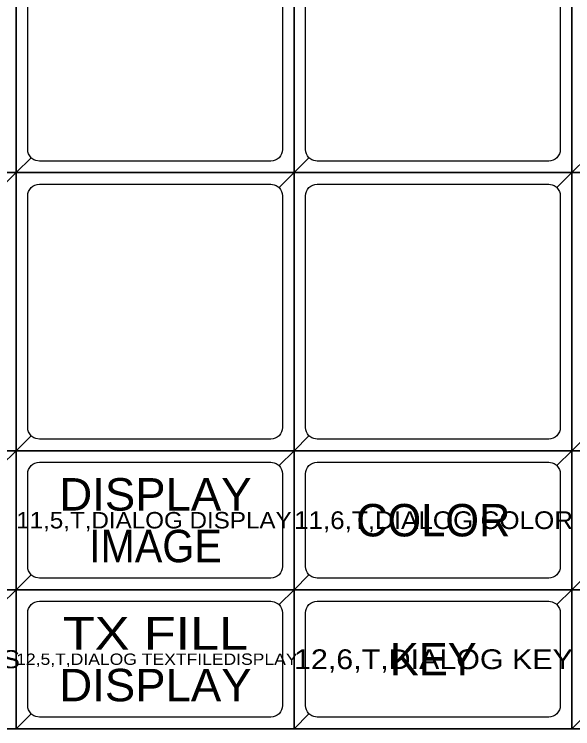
# Model space of a CAD drawing. Extents: x 67896 to 67908, y 49158.5 to 49162.6.
# Drawn here: x 67898.685 to 67899.891, y 49159.033 to 49160.575 of the extents above; entities that cross this region are included whole.
import ezdxf
from ezdxf.enums import TextEntityAlignment as Align

# ---------------------------------------------------------------- set-up
doc = ezdxf.new("R2010")
doc.units = 0
doc.header["$LTSCALE"] = 0.02
for name, color, linetype, lineweight in [('1', 7, 'Continuous', 25), ('2', 7, 'Continuous', 25), ('3', 7, 'Continuous', 25), ('4', 7, 'Continuous', 25), ('5', 7, 'Continuous', 25)]:
    doc.layers.add(name, color=color, linetype=linetype, lineweight=lineweight)
doc.layers.add('63', color=7, linetype='Continuous')

msp = doc.modelspace()

# ---------------------------------------------------------------- linework, layer by layer
at = {"layer": '1'}
for points in [[(67898.0889, 49160.2331), (67898.6889, 49160.2331), (67898.6889, 49160.8331), (67898.0889, 49160.8331)], [(67898.6889, 49160.2331), (67899.2889, 49160.2331), (67899.2889, 49160.8331), (67898.6889, 49160.8331)], [(67899.2889, 49160.2331), (67899.8889, 49160.2331), (67899.8889, 49160.8331), (67899.2889, 49160.8331)], [(67899.8889, 49160.2331), (67900.4889, 49160.2331), (67900.4889, 49160.8331), (67899.8889, 49160.8331)], [(67898.0889, 49159.6331), (67898.6889, 49159.6331), (67898.6889, 49160.2331), (67898.0889, 49160.2331)], [(67898.6889, 49159.6331), (67899.2889, 49159.6331), (67899.2889, 49160.2331), (67898.6889, 49160.2331)], [(67899.2889, 49159.6331), (67899.8889, 49159.6331), (67899.8889, 49160.2331), (67899.2889, 49160.2331)], [(67899.8889, 49159.6331), (67900.4889, 49159.6331), (67900.4889, 49160.2331), (67899.8889, 49160.2331)], [(67898.0889, 49159.3331), (67898.6889, 49159.3331), (67898.6889, 49159.6331), (67898.0889, 49159.6331)], [(67898.6889, 49159.3331), (67899.2889, 49159.3331), (67899.2889, 49159.6331), (67898.6889, 49159.6331)], [(67899.2889, 49159.3331), (67899.8889, 49159.3331), (67899.8889, 49159.6331), (67899.2889, 49159.6331)], [(67899.8889, 49159.3331), (67900.4889, 49159.3331), (67900.4889, 49159.6331), (67899.8889, 49159.6331)], [(67898.0889, 49159.0331), (67898.6889, 49159.0331), (67898.6889, 49159.3331), (67898.0889, 49159.3331)], [(67898.6889, 49159.0331), (67899.2889, 49159.0331), (67899.2889, 49159.3331), (67898.6889, 49159.3331)], [(67899.2889, 49159.0331), (67899.8889, 49159.0331), (67899.8889, 49159.3331), (67899.2889, 49159.3331)], [(67899.8889, 49159.0331), (67900.4889, 49159.0331), (67900.4889, 49159.3331), (67899.8889, 49159.3331)]]:
    msp.add_lwpolyline(points, close=True, dxfattribs=at)
at = {"layer": '2'}
for points in [[(67907.9889, 49159.0331), (67895.9889, 49159.0331), (67895.9889, 49162.6331), (67907.9889, 49162.6331)], [(67898.0889, 49160.2331), (67898.6889, 49160.2331), (67898.6889, 49160.8331), (67898.0889, 49160.8331)], [(67898.6889, 49160.2331), (67899.2889, 49160.2331), (67899.2889, 49160.8331), (67898.6889, 49160.8331)], [(67899.2889, 49160.2331), (67899.8889, 49160.2331), (67899.8889, 49160.8331), (67899.2889, 49160.8331)], [(67899.8889, 49160.2331), (67900.4889, 49160.2331), (67900.4889, 49160.8331), (67899.8889, 49160.8331)], [(67898.0889, 49159.6331), (67898.6889, 49159.6331), (67898.6889, 49160.2331), (67898.0889, 49160.2331)], [(67898.6889, 49159.6331), (67899.2889, 49159.6331), (67899.2889, 49160.2331), (67898.6889, 49160.2331)], [(67899.2889, 49159.6331), (67899.8889, 49159.6331), (67899.8889, 49160.2331), (67899.2889, 49160.2331)], [(67899.8889, 49159.6331), (67900.4889, 49159.6331), (67900.4889, 49160.2331), (67899.8889, 49160.2331)], [(67898.0889, 49159.3331), (67898.6889, 49159.3331), (67898.6889, 49159.6331), (67898.0889, 49159.6331)], [(67898.6889, 49159.3331), (67899.2889, 49159.3331), (67899.2889, 49159.6331), (67898.6889, 49159.6331)], [(67899.2889, 49159.3331), (67899.8889, 49159.3331), (67899.8889, 49159.6331), (67899.2889, 49159.6331)], [(67899.8889, 49159.3331), (67900.4889, 49159.3331), (67900.4889, 49159.6331), (67899.8889, 49159.6331)], [(67898.0889, 49159.0331), (67898.6889, 49159.0331), (67898.6889, 49159.3331), (67898.0889, 49159.3331)], [(67898.6889, 49159.0331), (67899.2889, 49159.0331), (67899.2889, 49159.3331), (67898.6889, 49159.3331)], [(67899.2889, 49159.0331), (67899.8889, 49159.0331), (67899.8889, 49159.3331), (67899.2889, 49159.3331)], [(67899.8889, 49159.0331), (67900.4889, 49159.0331), (67900.4889, 49159.3331), (67899.8889, 49159.3331)]]:
    msp.add_lwpolyline(points, close=True, dxfattribs=at)
at = {"layer": '3'}
for points in [[(67899.2889, 49160.8331), (67898.6889, 49160.8331), (67898.6889, 49160.2331), (67898.7212, 49160.2654), (67898.7181, 49160.2692), (67898.7158, 49160.2735), (67898.7144, 49160.2782), (67898.7139, 49160.2831), (67898.7139, 49160.7831), (67898.7144, 49160.788), (67898.7158, 49160.7927), (67898.7181, 49160.797), (67898.7212, 49160.8008), (67898.7212, 49160.8008), (67898.725, 49160.8039), (67898.7293, 49160.8062), (67898.734, 49160.8076), (67898.7389, 49160.8081), (67899.2389, 49160.8081), (67899.2462, 49160.807), (67899.2507, 49160.8051), (67899.2548, 49160.8024), (67899.2566, 49160.8008)], [(67899.8889, 49160.8331), (67899.2889, 49160.8331), (67899.2889, 49160.2331), (67899.3212, 49160.2654), (67899.3181, 49160.2692), (67899.3158, 49160.2735), (67899.3144, 49160.2782), (67899.3139, 49160.2831), (67899.3139, 49160.7831), (67899.3144, 49160.788), (67899.3158, 49160.7927), (67899.3181, 49160.797), (67899.3212, 49160.8008), (67899.3212, 49160.8008), (67899.325, 49160.8039), (67899.3293, 49160.8062), (67899.334, 49160.8076), (67899.3389, 49160.8081), (67899.8389, 49160.8081), (67899.8462, 49160.807), (67899.8507, 49160.8051), (67899.8548, 49160.8024), (67899.8566, 49160.8008)], [(67900.4889, 49160.8331), (67899.8889, 49160.8331), (67899.8889, 49160.2331), (67899.9212, 49160.2654), (67899.9181, 49160.2692), (67899.9158, 49160.2735), (67899.9144, 49160.2782), (67899.9139, 49160.2831), (67899.9139, 49160.7831), (67899.9144, 49160.788), (67899.9158, 49160.7927), (67899.9181, 49160.797), (67899.9212, 49160.8008), (67899.9212, 49160.8008), (67899.925, 49160.8039), (67899.9293, 49160.8062), (67899.934, 49160.8076), (67899.9389, 49160.8081), (67900.4389, 49160.8081), (67900.4462, 49160.807), (67900.4507, 49160.8051), (67900.4548, 49160.8024), (67900.4566, 49160.8008)], [(67898.6889, 49160.2331), (67898.0889, 49160.2331), (67898.0889, 49159.6331), (67898.1212, 49159.6654), (67898.1181, 49159.6692), (67898.1158, 49159.6735), (67898.1144, 49159.6782), (67898.1139, 49159.6831), (67898.1139, 49160.1831), (67898.1144, 49160.188), (67898.1158, 49160.1927), (67898.1181, 49160.197), (67898.1212, 49160.2008), (67898.1212, 49160.2008), (67898.125, 49160.2039), (67898.1293, 49160.2062), (67898.134, 49160.2076), (67898.1389, 49160.2081), (67898.6389, 49160.2081), (67898.6462, 49160.207), (67898.6507, 49160.2051), (67898.6548, 49160.2024), (67898.6566, 49160.2008)], [(67899.2889, 49160.2331), (67898.6889, 49160.2331), (67898.6889, 49159.6331), (67898.7212, 49159.6654), (67898.7181, 49159.6692), (67898.7158, 49159.6735), (67898.7144, 49159.6782), (67898.7139, 49159.6831), (67898.7139, 49160.1831), (67898.7144, 49160.188), (67898.7158, 49160.1927), (67898.7181, 49160.197), (67898.7212, 49160.2008), (67898.7212, 49160.2008), (67898.725, 49160.2039), (67898.7293, 49160.2062), (67898.734, 49160.2076), (67898.7389, 49160.2081), (67899.2389, 49160.2081), (67899.2462, 49160.207), (67899.2507, 49160.2051), (67899.2548, 49160.2024), (67899.2566, 49160.2008)], [(67899.8889, 49160.2331), (67899.2889, 49160.2331), (67899.2889, 49159.6331), (67899.3212, 49159.6654), (67899.3181, 49159.6692), (67899.3158, 49159.6735), (67899.3144, 49159.6782), (67899.3139, 49159.6831), (67899.3139, 49160.1831), (67899.3144, 49160.188), (67899.3158, 49160.1927), (67899.3181, 49160.197), (67899.3212, 49160.2008), (67899.3212, 49160.2008), (67899.325, 49160.2039), (67899.3293, 49160.2062), (67899.334, 49160.2076), (67899.3389, 49160.2081), (67899.8389, 49160.2081), (67899.8462, 49160.207), (67899.8507, 49160.2051), (67899.8548, 49160.2024), (67899.8566, 49160.2008)], [(67900.4889, 49160.2331), (67899.8889, 49160.2331), (67899.8889, 49159.6331), (67899.9212, 49159.6654), (67899.9181, 49159.6692), (67899.9158, 49159.6735), (67899.9144, 49159.6782), (67899.9139, 49159.6831), (67899.9139, 49160.1831), (67899.9144, 49160.188), (67899.9158, 49160.1927), (67899.9181, 49160.197), (67899.9212, 49160.2008), (67899.9212, 49160.2008), (67899.925, 49160.2039), (67899.9293, 49160.2062), (67899.934, 49160.2076), (67899.9389, 49160.2081), (67900.4389, 49160.2081), (67900.4462, 49160.207), (67900.4507, 49160.2051), (67900.4548, 49160.2024), (67900.4566, 49160.2008)], [(67898.6889, 49159.6331), (67898.0889, 49159.6331), (67898.0889, 49159.3331), (67898.1212, 49159.3654), (67898.1181, 49159.3692), (67898.1158, 49159.3735), (67898.1144, 49159.3782), (67898.1139, 49159.3831), (67898.1139, 49159.5831), (67898.1144, 49159.588), (67898.1158, 49159.5927), (67898.1181, 49159.597), (67898.1212, 49159.6008), (67898.1212, 49159.6008), (67898.125, 49159.6039), (67898.1293, 49159.6062), (67898.134, 49159.6076), (67898.1389, 49159.6081), (67898.6389, 49159.6081), (67898.6462, 49159.607), (67898.6507, 49159.6051), (67898.6548, 49159.6024), (67898.6566, 49159.6008)], [(67899.2889, 49159.6331), (67898.6889, 49159.6331), (67898.6889, 49159.3331), (67898.7212, 49159.3654), (67898.7181, 49159.3692), (67898.7158, 49159.3735), (67898.7144, 49159.3782), (67898.7139, 49159.3831), (67898.7139, 49159.5831), (67898.7144, 49159.588), (67898.7158, 49159.5927), (67898.7181, 49159.597), (67898.7212, 49159.6008), (67898.7212, 49159.6008), (67898.725, 49159.6039), (67898.7293, 49159.6062), (67898.734, 49159.6076), (67898.7389, 49159.6081), (67899.2389, 49159.6081), (67899.2462, 49159.607), (67899.2507, 49159.6051), (67899.2548, 49159.6024), (67899.2566, 49159.6008)], [(67899.8889, 49159.6331), (67899.2889, 49159.6331), (67899.2889, 49159.3331), (67899.3212, 49159.3654), (67899.3181, 49159.3692), (67899.3158, 49159.3735), (67899.3144, 49159.3782), (67899.3139, 49159.3831), (67899.3139, 49159.5831), (67899.3144, 49159.588), (67899.3158, 49159.5927), (67899.3181, 49159.597), (67899.3212, 49159.6008), (67899.3212, 49159.6008), (67899.325, 49159.6039), (67899.3293, 49159.6062), (67899.334, 49159.6076), (67899.3389, 49159.6081), (67899.8389, 49159.6081), (67899.8462, 49159.607), (67899.8507, 49159.6051), (67899.8548, 49159.6024), (67899.8566, 49159.6008)], [(67900.4889, 49159.6331), (67899.8889, 49159.6331), (67899.8889, 49159.3331), (67899.9212, 49159.3654), (67899.9181, 49159.3692), (67899.9158, 49159.3735), (67899.9144, 49159.3782), (67899.9139, 49159.3831), (67899.9139, 49159.5831), (67899.9144, 49159.588), (67899.9158, 49159.5927), (67899.9181, 49159.597), (67899.9212, 49159.6008), (67899.9212, 49159.6008), (67899.925, 49159.6039), (67899.9293, 49159.6062), (67899.934, 49159.6076), (67899.9389, 49159.6081), (67900.4389, 49159.6081), (67900.4462, 49159.607), (67900.4507, 49159.6051), (67900.4548, 49159.6024), (67900.4566, 49159.6008)], [(67898.6889, 49159.3331), (67898.0889, 49159.3331), (67898.0889, 49159.0331), (67898.1212, 49159.0654), (67898.1181, 49159.0692), (67898.1158, 49159.0735), (67898.1144, 49159.0782), (67898.1139, 49159.0831), (67898.1139, 49159.2831), (67898.1144, 49159.288), (67898.1158, 49159.2927), (67898.1181, 49159.297), (67898.1212, 49159.3008), (67898.1212, 49159.3008), (67898.125, 49159.3039), (67898.1293, 49159.3062), (67898.134, 49159.3076), (67898.1389, 49159.3081), (67898.6389, 49159.3081), (67898.6462, 49159.307), (67898.6507, 49159.3051), (67898.6548, 49159.3024), (67898.6566, 49159.3008)], [(67899.2889, 49159.3331), (67898.6889, 49159.3331), (67898.6889, 49159.0331), (67898.7212, 49159.0654), (67898.7181, 49159.0692), (67898.7158, 49159.0735), (67898.7144, 49159.0782), (67898.7139, 49159.0831), (67898.7139, 49159.2831), (67898.7144, 49159.288), (67898.7158, 49159.2927), (67898.7181, 49159.297), (67898.7212, 49159.3008), (67898.7212, 49159.3008), (67898.725, 49159.3039), (67898.7293, 49159.3062), (67898.734, 49159.3076), (67898.7389, 49159.3081), (67899.2389, 49159.3081), (67899.2462, 49159.307), (67899.2507, 49159.3051), (67899.2548, 49159.3024), (67899.2566, 49159.3008)], [(67899.8889, 49159.3331), (67899.2889, 49159.3331), (67899.2889, 49159.0331), (67899.3212, 49159.0654), (67899.3181, 49159.0692), (67899.3158, 49159.0735), (67899.3144, 49159.0782), (67899.3139, 49159.0831), (67899.3139, 49159.2831), (67899.3144, 49159.288), (67899.3158, 49159.2927), (67899.3181, 49159.297), (67899.3212, 49159.3008), (67899.3212, 49159.3008), (67899.325, 49159.3039), (67899.3293, 49159.3062), (67899.334, 49159.3076), (67899.3389, 49159.3081), (67899.8389, 49159.3081), (67899.8462, 49159.307), (67899.8507, 49159.3051), (67899.8548, 49159.3024), (67899.8566, 49159.3008)], [(67900.4889, 49159.3331), (67899.8889, 49159.3331), (67899.8889, 49159.0331), (67899.9212, 49159.0654), (67899.9181, 49159.0692), (67899.9158, 49159.0735), (67899.9144, 49159.0782), (67899.9139, 49159.0831), (67899.9139, 49159.2831), (67899.9144, 49159.288), (67899.9158, 49159.2927), (67899.9181, 49159.297), (67899.9212, 49159.3008), (67899.9212, 49159.3008), (67899.925, 49159.3039), (67899.9293, 49159.3062), (67899.934, 49159.3076), (67899.9389, 49159.3081), (67900.4389, 49159.3081), (67900.4462, 49159.307), (67900.4507, 49159.3051), (67900.4548, 49159.3024), (67900.4566, 49159.3008)]]:
    msp.add_lwpolyline(points, close=True, dxfattribs=at)
at = {"layer": '4'}
for points in [[(67898.0889, 49160.2331), (67898.6889, 49160.2331), (67898.6889, 49160.8331), (67898.6566, 49160.8008), (67898.6597, 49160.797), (67898.662, 49160.7927), (67898.6634, 49160.788), (67898.6639, 49160.7831), (67898.6639, 49160.2831), (67898.6634, 49160.2782), (67898.662, 49160.2735), (67898.6597, 49160.2692), (67898.6566, 49160.2654), (67898.6566, 49160.2654), (67898.6528, 49160.2623), (67898.6485, 49160.26), (67898.6438, 49160.2586), (67898.6389, 49160.2581), (67898.1389, 49160.2581), (67898.1316, 49160.2592), (67898.1271, 49160.2611), (67898.123, 49160.2638), (67898.1212, 49160.2654)], [(67898.6889, 49160.2331), (67899.2889, 49160.2331), (67899.2889, 49160.8331), (67899.2566, 49160.8008), (67899.2597, 49160.797), (67899.262, 49160.7927), (67899.2634, 49160.788), (67899.2639, 49160.7831), (67899.2639, 49160.2831), (67899.2634, 49160.2782), (67899.262, 49160.2735), (67899.2597, 49160.2692), (67899.2566, 49160.2654), (67899.2566, 49160.2654), (67899.2528, 49160.2623), (67899.2485, 49160.26), (67899.2438, 49160.2586), (67899.2389, 49160.2581), (67898.7389, 49160.2581), (67898.7316, 49160.2592), (67898.7271, 49160.2611), (67898.723, 49160.2638), (67898.7212, 49160.2654)], [(67899.2889, 49160.2331), (67899.8889, 49160.2331), (67899.8889, 49160.8331), (67899.8566, 49160.8008), (67899.8597, 49160.797), (67899.862, 49160.7927), (67899.8634, 49160.788), (67899.8639, 49160.7831), (67899.8639, 49160.2831), (67899.8634, 49160.2782), (67899.862, 49160.2735), (67899.8597, 49160.2692), (67899.8566, 49160.2654), (67899.8566, 49160.2654), (67899.8528, 49160.2623), (67899.8485, 49160.26), (67899.8438, 49160.2586), (67899.8389, 49160.2581), (67899.3389, 49160.2581), (67899.3316, 49160.2592), (67899.3271, 49160.2611), (67899.323, 49160.2638), (67899.3212, 49160.2654)], [(67899.8889, 49160.2331), (67900.4889, 49160.2331), (67900.4889, 49160.8331), (67900.4566, 49160.8008), (67900.4597, 49160.797), (67900.462, 49160.7927), (67900.4634, 49160.788), (67900.4639, 49160.7831), (67900.4639, 49160.2831), (67900.4634, 49160.2782), (67900.462, 49160.2735), (67900.4597, 49160.2692), (67900.4566, 49160.2654), (67900.4566, 49160.2654), (67900.4528, 49160.2623), (67900.4485, 49160.26), (67900.4438, 49160.2586), (67900.4389, 49160.2581), (67899.9389, 49160.2581), (67899.9316, 49160.2592), (67899.9271, 49160.2611), (67899.923, 49160.2638), (67899.9212, 49160.2654)], [(67898.0889, 49159.6331), (67898.6889, 49159.6331), (67898.6889, 49160.2331), (67898.6566, 49160.2008), (67898.6597, 49160.197), (67898.662, 49160.1927), (67898.6634, 49160.188), (67898.6639, 49160.1831), (67898.6639, 49159.6831), (67898.6634, 49159.6782), (67898.662, 49159.6735), (67898.6597, 49159.6692), (67898.6566, 49159.6654), (67898.6566, 49159.6654), (67898.6528, 49159.6623), (67898.6485, 49159.66), (67898.6438, 49159.6586), (67898.6389, 49159.6581), (67898.1389, 49159.6581), (67898.1316, 49159.6592), (67898.1271, 49159.6611), (67898.123, 49159.6638), (67898.1212, 49159.6654)], [(67898.6889, 49159.6331), (67899.2889, 49159.6331), (67899.2889, 49160.2331), (67899.2566, 49160.2008), (67899.2597, 49160.197), (67899.262, 49160.1927), (67899.2634, 49160.188), (67899.2639, 49160.1831), (67899.2639, 49159.6831), (67899.2634, 49159.6782), (67899.262, 49159.6735), (67899.2597, 49159.6692), (67899.2566, 49159.6654), (67899.2566, 49159.6654), (67899.2528, 49159.6623), (67899.2485, 49159.66), (67899.2438, 49159.6586), (67899.2389, 49159.6581), (67898.7389, 49159.6581), (67898.7316, 49159.6592), (67898.7271, 49159.6611), (67898.723, 49159.6638), (67898.7212, 49159.6654)], [(67899.2889, 49159.6331), (67899.8889, 49159.6331), (67899.8889, 49160.2331), (67899.8566, 49160.2008), (67899.8597, 49160.197), (67899.862, 49160.1927), (67899.8634, 49160.188), (67899.8639, 49160.1831), (67899.8639, 49159.6831), (67899.8634, 49159.6782), (67899.862, 49159.6735), (67899.8597, 49159.6692), (67899.8566, 49159.6654), (67899.8566, 49159.6654), (67899.8528, 49159.6623), (67899.8485, 49159.66), (67899.8438, 49159.6586), (67899.8389, 49159.6581), (67899.3389, 49159.6581), (67899.3316, 49159.6592), (67899.3271, 49159.6611), (67899.323, 49159.6638), (67899.3212, 49159.6654)], [(67899.8889, 49159.6331), (67900.4889, 49159.6331), (67900.4889, 49160.2331), (67900.4566, 49160.2008), (67900.4597, 49160.197), (67900.462, 49160.1927), (67900.4634, 49160.188), (67900.4639, 49160.1831), (67900.4639, 49159.6831), (67900.4634, 49159.6782), (67900.462, 49159.6735), (67900.4597, 49159.6692), (67900.4566, 49159.6654), (67900.4566, 49159.6654), (67900.4528, 49159.6623), (67900.4485, 49159.66), (67900.4438, 49159.6586), (67900.4389, 49159.6581), (67899.9389, 49159.6581), (67899.9316, 49159.6592), (67899.9271, 49159.6611), (67899.923, 49159.6638), (67899.9212, 49159.6654)], [(67898.0889, 49159.3331), (67898.6889, 49159.3331), (67898.6889, 49159.6331), (67898.6566, 49159.6008), (67898.6597, 49159.597), (67898.662, 49159.5927), (67898.6634, 49159.588), (67898.6639, 49159.5831), (67898.6639, 49159.3831), (67898.6634, 49159.3782), (67898.662, 49159.3735), (67898.6597, 49159.3692), (67898.6566, 49159.3654), (67898.6566, 49159.3654), (67898.6528, 49159.3623), (67898.6485, 49159.36), (67898.6438, 49159.3586), (67898.6389, 49159.3581), (67898.1389, 49159.3581), (67898.1316, 49159.3592), (67898.1271, 49159.3611), (67898.123, 49159.3638), (67898.1212, 49159.3654)], [(67898.6889, 49159.3331), (67899.2889, 49159.3331), (67899.2889, 49159.6331), (67899.2566, 49159.6008), (67899.2597, 49159.597), (67899.262, 49159.5927), (67899.2634, 49159.588), (67899.2639, 49159.5831), (67899.2639, 49159.3831), (67899.2634, 49159.3782), (67899.262, 49159.3735), (67899.2597, 49159.3692), (67899.2566, 49159.3654), (67899.2566, 49159.3654), (67899.2528, 49159.3623), (67899.2485, 49159.36), (67899.2438, 49159.3586), (67899.2389, 49159.3581), (67898.7389, 49159.3581), (67898.7316, 49159.3592), (67898.7271, 49159.3611), (67898.723, 49159.3638), (67898.7212, 49159.3654)], [(67899.2889, 49159.3331), (67899.8889, 49159.3331), (67899.8889, 49159.6331), (67899.8566, 49159.6008), (67899.8597, 49159.597), (67899.862, 49159.5927), (67899.8634, 49159.588), (67899.8639, 49159.5831), (67899.8639, 49159.3831), (67899.8634, 49159.3782), (67899.862, 49159.3735), (67899.8597, 49159.3692), (67899.8566, 49159.3654), (67899.8566, 49159.3654), (67899.8528, 49159.3623), (67899.8485, 49159.36), (67899.8438, 49159.3586), (67899.8389, 49159.3581), (67899.3389, 49159.3581), (67899.3316, 49159.3592), (67899.3271, 49159.3611), (67899.323, 49159.3638), (67899.3212, 49159.3654)], [(67899.8889, 49159.3331), (67900.4889, 49159.3331), (67900.4889, 49159.6331), (67900.4566, 49159.6008), (67900.4597, 49159.597), (67900.462, 49159.5927), (67900.4634, 49159.588), (67900.4639, 49159.5831), (67900.4639, 49159.3831), (67900.4634, 49159.3782), (67900.462, 49159.3735), (67900.4597, 49159.3692), (67900.4566, 49159.3654), (67900.4566, 49159.3654), (67900.4528, 49159.3623), (67900.4485, 49159.36), (67900.4438, 49159.3586), (67900.4389, 49159.3581), (67899.9389, 49159.3581), (67899.9316, 49159.3592), (67899.9271, 49159.3611), (67899.923, 49159.3638), (67899.9212, 49159.3654)], [(67898.0889, 49159.0331), (67898.6889, 49159.0331), (67898.6889, 49159.3331), (67898.6566, 49159.3008), (67898.6597, 49159.297), (67898.662, 49159.2927), (67898.6634, 49159.288), (67898.6639, 49159.2831), (67898.6639, 49159.0831), (67898.6634, 49159.0782), (67898.662, 49159.0735), (67898.6597, 49159.0692), (67898.6566, 49159.0654), (67898.6566, 49159.0654), (67898.6528, 49159.0623), (67898.6485, 49159.06), (67898.6438, 49159.0586), (67898.6389, 49159.0581), (67898.1389, 49159.0581), (67898.1316, 49159.0592), (67898.1271, 49159.0611), (67898.123, 49159.0638), (67898.1212, 49159.0654)], [(67898.6889, 49159.0331), (67899.2889, 49159.0331), (67899.2889, 49159.3331), (67899.2566, 49159.3008), (67899.2597, 49159.297), (67899.262, 49159.2927), (67899.2634, 49159.288), (67899.2639, 49159.2831), (67899.2639, 49159.0831), (67899.2634, 49159.0782), (67899.262, 49159.0735), (67899.2597, 49159.0692), (67899.2566, 49159.0654), (67899.2566, 49159.0654), (67899.2528, 49159.0623), (67899.2485, 49159.06), (67899.2438, 49159.0586), (67899.2389, 49159.0581), (67898.7389, 49159.0581), (67898.7316, 49159.0592), (67898.7271, 49159.0611), (67898.723, 49159.0638), (67898.7212, 49159.0654)], [(67899.2889, 49159.0331), (67899.8889, 49159.0331), (67899.8889, 49159.3331), (67899.8566, 49159.3008), (67899.8597, 49159.297), (67899.862, 49159.2927), (67899.8634, 49159.288), (67899.8639, 49159.2831), (67899.8639, 49159.0831), (67899.8634, 49159.0782), (67899.862, 49159.0735), (67899.8597, 49159.0692), (67899.8566, 49159.0654), (67899.8566, 49159.0654), (67899.8528, 49159.0623), (67899.8485, 49159.06), (67899.8438, 49159.0586), (67899.8389, 49159.0581), (67899.3389, 49159.0581), (67899.3316, 49159.0592), (67899.3271, 49159.0611), (67899.323, 49159.0638), (67899.3212, 49159.0654)], [(67899.8889, 49159.0331), (67900.4889, 49159.0331), (67900.4889, 49159.3331), (67900.4566, 49159.3008), (67900.4597, 49159.297), (67900.462, 49159.2927), (67900.4634, 49159.288), (67900.4639, 49159.2831), (67900.4639, 49159.0831), (67900.4634, 49159.0782), (67900.462, 49159.0735), (67900.4597, 49159.0692), (67900.4566, 49159.0654), (67900.4566, 49159.0654), (67900.4528, 49159.0623), (67900.4485, 49159.06), (67900.4438, 49159.0586), (67900.4389, 49159.0581), (67899.9389, 49159.0581), (67899.9316, 49159.0592), (67899.9271, 49159.0611), (67899.923, 49159.0638), (67899.9212, 49159.0654)]]:
    msp.add_lwpolyline(points, close=True, dxfattribs=at)

# ---------------------------------------------------------------- texts
at = {"layer": '5'}
for s, width, p in [('DISPLAY', 1.05, (67898.9897, 49159.5039)), ('IMAGE', 0.95, (67898.9897, 49159.3923)), ('TX FILL', 1.2, (67898.9897, 49159.204)), ('DISPLAY', 1.05, (67898.9897, 49159.0923))]:
    msp.add_text(s, height=0.07, dxfattribs=dict(at, width=width)).set_placement(p, align=Align.CENTER)
for s, p in [('COLOR', (67899.5897, 49159.4481)), ('KEY', (67899.5897, 49159.1481))]:
    msp.add_text(s, height=0.07, dxfattribs=at).set_placement(p, align=Align.CENTER)
at = {"layer": '63'}
for s, height, width, p in [('11,5,T,DIALOG DISPLAY', 0.0355, 1.1, (67898.6889, 49159.4653)), ('11,6,T,DIALOG COLOR', 0.0382, 1.1, (67899.2889, 49159.464)), ('12,6,T,DIALOG KEY', 0.0427, 1.15, (67899.2889, 49159.1617)), ('12,4,T,DIALOG UNITS', 0.0389, 1.15, (67898.0889, 49159.1636)), ('12,5,T,DIALOG TEXTFILEDISPLAY', 0.0246, 1.15, (67898.6889, 49159.1708))]:
    msp.add_text(s, height=height, dxfattribs=dict(at, width=width)).set_placement(p)

doc.saveas('drawing.dxf')
